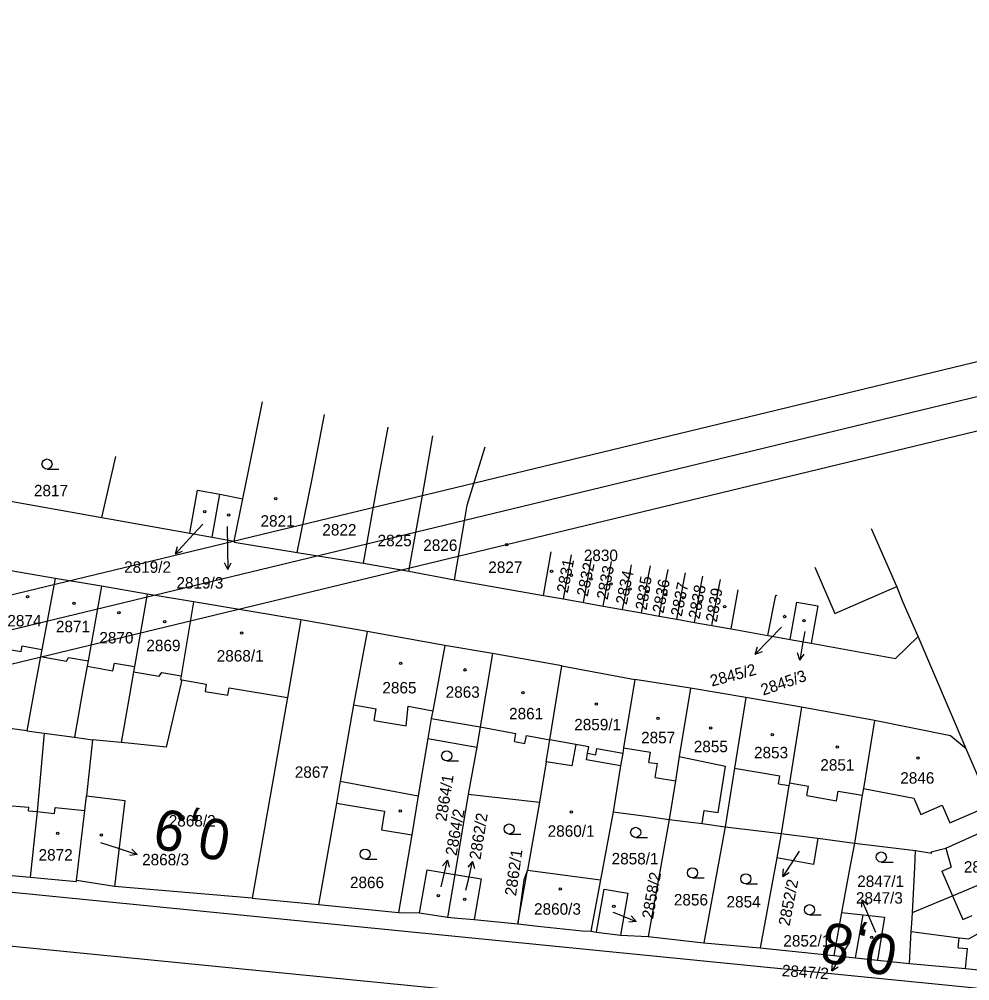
# Model space of a CAD drawing. Extents: x -738085 to -734306, y -1122197 to -1119753.
# Drawn here: x -734886.7 to -734745.8, y -1120127 to -1119984.4 of the extents above; entities that cross this region are included whole.
import ezdxf

# ---------------------------------------------------------------- set-up
doc = ezdxf.new("R2010")
doc.units = 0
for name, color, linetype in [('Hranice parcel', 7, 'Continuous'), ('Parcelní čísla', 7, 'Continuous'), ('Pop  PČ popisy', 7, 'Continuous'), ('Vnitřní kresba', 7, 'Continuous'), ('Vrstva 1', 7, 'Continuous'), ('Vrstva 7', 7, 'Continuous'), ('Značky budov', 7, 'Continuous'), ('Značky kultur', 7, 'Continuous')]:
    doc.layers.add(name, color=color, linetype=linetype)

msp = doc.modelspace()

# ---------------------------------------------------------------- linework, layer by layer
at = {"layer": 'Hranice parcel'}
for p, q in [((-734874.44, -1120058.28), (-734872.37, -1120049.21)), ((-734893, -1120054.98), (-734874.44, -1120058.28)), ((-734858.08, -1120061.19), (-734856.95, -1120054.8)), ((-734856.95, -1120054.8), (-734853.51, -1120055.5)), ((-734854.79, -1120061.77), (-734853.51, -1120055.5)), ((-734874.44, -1120058.28), (-734861.39, -1120060.6)), ((-734861.39, -1120060.6), (-734858.08, -1120061.19)), ((-734858.08, -1120061.19), (-734854.79, -1120061.77)), ((-734845.44, -1120063.49), (-734835.62, -1120065.05)), ((-734808.93, -1120069.83), (-734807.8, -1120063.35)), ((-734805.99, -1120070.36), (-734804.82, -1120063.83)), ((-734803.04, -1120070.88), (-734801.85, -1120064.32)), ((-734800.1, -1120071.41), (-734798.88, -1120064.8)), ((-734881.34, -1120067.31), (-734887.91, -1120066.19)), ((-734835.62, -1120065.05), (-734828.89, -1120066.24)), ((-734828.89, -1120066.24), (-734822.16, -1120067.53)), ((-734874.49, -1120068.47), (-734881.34, -1120067.31)), ((-734822.16, -1120067.53), (-734808.93, -1120069.83)), ((-734867.71, -1120069.63), (-734874.49, -1120068.47)), ((-734860.82, -1120070.8), (-734867.71, -1120069.63)), ((-734808.93, -1120069.83), (-734805.99, -1120070.36)), ((-734805.99, -1120070.36), (-734803.04, -1120070.88)), ((-734844.9, -1120073.45), (-734860.82, -1120070.8)), ((-734803.04, -1120070.88), (-734800.1, -1120071.41)), ((-734800.1, -1120071.41), (-734797.25, -1120071.92)), ((-734797.25, -1120071.92), (-734794.41, -1120072.43)), ((-734772.36, -1120076.38), (-734771.37, -1120070.82)), ((-734844.9, -1120073.45), (-734846.88, -1120084.98)), ((-734835.1, -1120075.16), (-734844.9, -1120073.45)), ((-734794.41, -1120072.43), (-734791.8, -1120072.9)), ((-734791.8, -1120072.9), (-734789.18, -1120073.36)), ((-734789.18, -1120073.36), (-734786.58, -1120073.83)), ((-734786.58, -1120073.83), (-734783.98, -1120074.29)), ((-734823.55, -1120077.28), (-734835.1, -1120075.16)), ((-734772.36, -1120076.38), (-734769.29, -1120076.93)), ((-734746.27, -1120092.6), (-734753.42, -1120075.94)), ((-734816.52, -1120078.43), (-734823.55, -1120077.28)), ((-734806.22, -1120080.28), (-734816.52, -1120078.43)), ((-734806.22, -1120080.28), (-734795.41, -1120082.28)), ((-734787.16, -1120083.57), (-734795.41, -1120082.28)), ((-734778.96, -1120084.96), (-734787.16, -1120083.57)), ((-734770.72, -1120086.41), (-734778.96, -1120084.96)), ((-734846.88, -1120084.98), (-734852.12, -1120114.74)), ((-734759.88, -1120088.36), (-734770.72, -1120086.41)), ((-734885.55, -1120089.9), (-734892.21, -1120088.99)), ((-734885.55, -1120089.9), (-734882.98, -1120090.25)), ((-734882.98, -1120090.25), (-734878.49, -1120090.86)), ((-734878.49, -1120090.86), (-734875.79, -1120091.23)), ((-734875.79, -1120091.23), (-734876.71, -1120099.56)), ((-734871.55, -1120091.66), (-734875.79, -1120091.23)), ((-734826.08, -1120091.05), (-734818.85, -1120092.33)), ((-734818.85, -1120092.33), (-734820.11, -1120099.3)), ((-734808.57, -1120094.5), (-734809.56, -1120100.51)), ((-734797.51, -1120095.11), (-734798.62, -1120101.92)), ((-734839.64, -1120100.63), (-734842.28, -1120115.65)), ((-734820.11, -1120099.3), (-734822.09, -1120111.23)), ((-734820.11, -1120099.3), (-734809.56, -1120100.51)), ((-734809.56, -1120100.51), (-734811.34, -1120110.59)), ((-734798.62, -1120101.92), (-734800.51, -1120112.02)), ((-734790.32, -1120103.04), (-734793.44, -1120120.43)), ((-734782.01, -1120104.13), (-734785.17, -1120121.34)), ((-734782.01, -1120104.13), (-734773.69, -1120105.13)), ((-734828.49, -1120105.32), (-734830.44, -1120116.83)), ((-734773.69, -1120105.13), (-734774.36, -1120108.76)), ((-734773.69, -1120105.13), (-734768.28, -1120105.84)), ((-734768.28, -1120105.84), (-734762.86, -1120106.55)), ((-734762.86, -1120106.55), (-734753.79, -1120107.64)), ((-734774.36, -1120108.76), (-734776.81, -1120122.08)), ((-734811.34, -1120110.59), (-734800.51, -1120112.02)), ((-734894.05, -1120110.78), (-734885.03, -1120111.61)), ((-734800.51, -1120112.02), (-734801.94, -1120119.63)), ((-734872.52, -1120112.98), (-734878.17, -1120112.12)), ((-734852.12, -1120114.74), (-734872.52, -1120112.98)), ((-734852.12, -1120114.74), (-734842.28, -1120115.65)), ((-734842.28, -1120115.65), (-734830.44, -1120116.83)), ((-734830.44, -1120116.83), (-734827.33, -1120116.92)), ((-734827.33, -1120116.92), (-734823.17, -1120117.53)), ((-734764.76, -1120116.86), (-734765.93, -1120123.22)), ((-734764.76, -1120116.86), (-734761.58, -1120117.21)), ((-734762.69, -1120123.56), (-734761.58, -1120117.21)), ((-734819.22, -1120117.87), (-734812.75, -1120118.54)), ((-734801.94, -1120119.63), (-734801.07, -1120119.77)), ((-734801.07, -1120119.77), (-734797.51, -1120120.19)), ((-734797.51, -1120120.19), (-734793.44, -1120120.43)), ((-734754.69, -1120124.4), (-734754.43, -1120119.69)), ((-734785.17, -1120121.34), (-734776.81, -1120122.08)), ((-734776.81, -1120122.08), (-734765.93, -1120123.22)), ((-734765.93, -1120123.22), (-734762.69, -1120123.56)), ((-734762.69, -1120123.56), (-734759.45, -1120123.9)), ((-734759.45, -1120123.9), (-734754.69, -1120124.4))]:
    msp.add_line(p, q, dxfattribs=at)
for points in [[(-734853.51, -1120055.5), (-734852.58, -1120050.93), (-734850.58, -1120041.13)], [(-734845.44, -1120063.49), (-734843.26, -1120052.53), (-734841.43, -1120042.99)], [(-734835.62, -1120065.05), (-734833.71, -1120054.16), (-734831.99, -1120044.9)], [(-734828.89, -1120066.24), (-734826.91, -1120055.32), (-734825.35, -1120046.18)], [(-734822.16, -1120067.53), (-734820.57, -1120058.24), (-734820.26, -1120056.46), (-734817.58, -1120047.82)], [(-734861.39, -1120060.6), (-734860.26, -1120054.21), (-734856.95, -1120054.8)], [(-734753.42, -1120075.94), (-734755.61, -1120070.88), (-734756.59, -1120068.49), (-734760.34, -1120059.94)], [(-734854.79, -1120061.77), (-734854.82, -1120061.93), (-734845.44, -1120063.49)], [(-734797.25, -1120071.92), (-734796.02, -1120065.89), (-734795.9, -1120065.28)], [(-734794.41, -1120072.43), (-734793.26, -1120066.43), (-734793.07, -1120065.46)], [(-734791.8, -1120072.9), (-734790.67, -1120066.94), (-734790.48, -1120065.97)], [(-734881.34, -1120067.31), (-734883.33, -1120077.85), (-734883.5, -1120078.88), (-734884.14, -1120082.31), (-734885.55, -1120089.9)], [(-734789.18, -1120073.36), (-734788.08, -1120067.45), (-734787.89, -1120066.48)], [(-734786.58, -1120073.83), (-734785.5, -1120067.96), (-734785.31, -1120066.99)], [(-734783.98, -1120074.29), (-734782.92, -1120068.47), (-734782.73, -1120067.49)], [(-734874.49, -1120068.47), (-734876.47, -1120079.55), (-734876.61, -1120080.32), (-734877.23, -1120083.78), (-734878.49, -1120090.86)], [(-734867.71, -1120069.63), (-734869.58, -1120080.38), (-734869.72, -1120081.15), (-734870.32, -1120084.61), (-734871.55, -1120091.66)], [(-734775.69, -1120075.78), (-734774.51, -1120069.82), (-734774.35, -1120069.85)], [(-734860.82, -1120070.8), (-734862.64, -1120081.76), (-734862.74, -1120082.33), (-734862.58, -1120082.36)], [(-734771.37, -1120070.82), (-734768.3, -1120071.37), (-734769.29, -1120076.93)], [(-734783.98, -1120074.29), (-734781.14, -1120074.8), (-734775.69, -1120075.78)], [(-734835.1, -1120075.16), (-734837.09, -1120086.08), (-734839.07, -1120097.38), (-734839.64, -1120100.63)], [(-734775.69, -1120075.78), (-734775.36, -1120075.84), (-734772.36, -1120076.38)], [(-734769.29, -1120076.93), (-734756.74, -1120079.17), (-734753.42, -1120075.94)], [(-734823.55, -1120077.28), (-734825.37, -1120086.94), (-734825.58, -1120088.08), (-734826.08, -1120091.05)], [(-734816.52, -1120078.43), (-734818.33, -1120089.33), (-734818.85, -1120092.33)], [(-734808.57, -1120094.5), (-734808.03, -1120091.23), (-734806.22, -1120080.28)], [(-734862.58, -1120082.36), (-734864.87, -1120092.33), (-734870.01, -1120091.81), (-734871.55, -1120091.66)], [(-734862.58, -1120082.36), (-734858.94, -1120082.97), (-734859.12, -1120084.06), (-734855.72, -1120084.64), (-734855.53, -1120083.53), (-734846.88, -1120084.98)], [(-734795.41, -1120082.28), (-734797.07, -1120092.45), (-734797.2, -1120093.23), (-734797.51, -1120095.11)], [(-734787.16, -1120083.57), (-734788.81, -1120093.71), (-734789.39, -1120097.33), (-734790.32, -1120103.04)], [(-734778.96, -1120084.96), (-734780.63, -1120095.44), (-734782.01, -1120104.13)], [(-734770.72, -1120086.41), (-734772.5, -1120097.61), (-734772.56, -1120098.03), (-734773.69, -1120105.13)], [(-734759.88, -1120088.36), (-734761.53, -1120098.46), (-734761.7, -1120099.46), (-734762.86, -1120106.55)], [(-734746.27, -1120092.6), (-734748.62, -1120090.64), (-734759.88, -1120088.36)], [(-734882.98, -1120090.25), (-734884.03, -1120101.9), (-734885.03, -1120111.61)], [(-734826.08, -1120091.05), (-734827.52, -1120099.56), (-734828.49, -1120105.32)], [(-734797.51, -1120095.11), (-734802.57, -1120094.22), (-734802.4, -1120093.24), (-734802.22, -1120092.3), (-734804.16, -1120091.94), (-734804.75, -1120095.12), (-734808.57, -1120094.5)], [(-734741.41, -1120103.73), (-734742.65, -1120100.94), (-734743.81, -1120098.34), (-734746.27, -1120092.6)], [(-734878.17, -1120112.12), (-734876.95, -1120101.73), (-734876.71, -1120099.56)], [(-734876.71, -1120099.56), (-734871.01, -1120100.25), (-734872.52, -1120112.98)], [(-734839.64, -1120100.63), (-734832.51, -1120101.83), (-734832.97, -1120104.57), (-734828.49, -1120105.32)], [(-734798.62, -1120101.92), (-734793.71, -1120102.56), (-734790.32, -1120103.04)], [(-734732.31, -1120124.29), (-734735.07, -1120127.22), (-734738.9, -1120128.4), (-734741.96, -1120128.37), (-734978.31, -1120104.89), (-734995.05, -1120103.5), (-735001.08, -1120103.64), (-735005.96, -1120104.65), (-735026.65, -1120111.99), (-735048.37, -1120119.26), (-735164.14, -1120157.32), (-735176.88, -1120160.91), (-735184.81, -1120162.43), (-735185.96, -1120162.53), (-735190.85, -1120162.98), (-735196.87, -1120162.75), (-735201.79, -1120161.48), (-735203.71, -1120160.98), (-735206.41, -1120159.5), (-735208.64, -1120157.56), (-735225.14, -1120141.26)], [(-734790.32, -1120103.04), (-734785.41, -1120103.64), (-734782.01, -1120104.13)], [(-734753.79, -1120107.64), (-734751.4, -1120108.03), (-734751.46, -1120107.88), (-734749.29, -1120107.32), (-734741.41, -1120103.73)], [(-734768.28, -1120105.84), (-734768.92, -1120109.73), (-734774.36, -1120108.76)], [(-734762.86, -1120106.55), (-734763.62, -1120110.68), (-734764.76, -1120116.86)], [(-734754.25, -1120116.86), (-734754.12, -1120114.04), (-734753.92, -1120110.19), (-734753.79, -1120107.64)], [(-734827.33, -1120116.92), (-734827.28, -1120116.65), (-734826.18, -1120110.52), (-734822.09, -1120111.23)], [(-734811.34, -1120110.59), (-734811.85, -1120111.99), (-734812.75, -1120118.54)], [(-734754.25, -1120116.86), (-734748.32, -1120114.37), (-734738.55, -1120110.28)], [(-735187.2, -1120177.07), (-735186.92, -1120175.94), (-735186.47, -1120174.12), (-735185.21, -1120172.48), (-735182.42, -1120171.13), (-735165.98, -1120166.38), (-735013.95, -1120116.34), (-735003.48, -1120113.01), (-735000.64, -1120112.19), (-735000, -1120112.13), (-734996.62, -1120111.83), (-734988.63, -1120112.11), (-734951.68, -1120115.51), (-734795.1, -1120131), (-734756.12, -1120134.99), (-734754.2, -1120137.32), (-734753.31, -1120137.78), (-734734.93, -1120139.52), (-734728.17, -1120141.08), (-734724.68, -1120142.84), (-734723.73, -1120143.69)], [(-734885.03, -1120111.61), (-734878.18, -1120112.24), (-734878.17, -1120112.12)], [(-734822.09, -1120111.23), (-734823.15, -1120117.32), (-734823.17, -1120117.53)], [(-734822.09, -1120111.23), (-734818.2, -1120111.85), (-734819.22, -1120117.87)], [(-734801.07, -1120119.77), (-734799.95, -1120113.38), (-734796.45, -1120113.97), (-734797.51, -1120120.19)], [(-734823.17, -1120117.53), (-734821.66, -1120117.71), (-734819.22, -1120117.87)], [(-734761.58, -1120117.21), (-734758.4, -1120117.56), (-734759.45, -1120123.9)], [(-734754.43, -1120119.69), (-734747.32, -1120120.59), (-734745.89, -1120120.77), (-734744.27, -1120119.8), (-734735.7, -1120116.71)], [(-734754.43, -1120119.69), (-734754.35, -1120118.5), (-734754.25, -1120116.86)], [(-734812.75, -1120118.54), (-734809.77, -1120118.87), (-734803.22, -1120119.55), (-734801.94, -1120119.63)], [(-734793.44, -1120120.43), (-734791.72, -1120120.63), (-734785.17, -1120121.34)], [(-734754.69, -1120124.4), (-734746.39, -1120125.14), (-734738.56, -1120125.97), (-734734.16, -1120120.2)]]:
    msp.add_lwpolyline(points, dxfattribs=at)
at = {"layer": 'Pop  PČ popisy'}
for p, q in [((-734859.47, -1120059.28), (-734861.47, -1120061.45)), ((-734855.83, -1120059.6), (-734855.79, -1120062.99)), ((-734861.47, -1120061.45), (-734863.52, -1120063.65)), ((-734863.52, -1120063.65), (-734863.2, -1120062.57)), ((-734863.52, -1120063.65), (-734862.47, -1120063.25)), ((-734855.79, -1120062.99), (-734855.74, -1120065.99)), ((-734855.74, -1120065.99), (-734856.26, -1120065)), ((-734855.74, -1120065.99), (-734855.25, -1120064.98)), ((-734773.66, -1120074.55), (-734775.46, -1120076.38)), ((-734775.46, -1120076.38), (-734777.55, -1120078.54)), ((-734770.21, -1120075.2), (-734770.45, -1120076.48)), ((-734777.55, -1120078.54), (-734777.21, -1120077.47)), ((-734770.45, -1120076.48), (-734770.97, -1120079.44)), ((-734777.55, -1120078.54), (-734776.49, -1120078.17)), ((-734770.97, -1120079.44), (-734771.29, -1120078.36)), ((-734770.97, -1120079.44), (-734770.3, -1120078.54)), ((-734874.64, -1120106.48), (-734872.02, -1120107.31)), ((-734872.02, -1120107.31), (-734869.17, -1120108.24)), ((-734869.17, -1120108.24), (-734869.96, -1120107.45)), ((-734771.06, -1120107.75), (-734771.86, -1120108.99)), ((-734869.17, -1120108.24), (-734870.27, -1120108.4)), ((-734823.19, -1120109.07), (-734823.9, -1120109.93)), ((-734823.86, -1120111.99), (-734823.19, -1120109.07)), ((-734823.19, -1120109.07), (-734822.92, -1120110.15)), ((-734771.86, -1120108.99), (-734773.49, -1120111.51)), ((-734819.45, -1120109.27), (-734820.17, -1120110.13)), ((-734820.13, -1120112.19), (-734819.45, -1120109.27)), ((-734819.45, -1120109.27), (-734819.19, -1120110.35)), ((-734773.49, -1120111.51), (-734773.37, -1120110.39)), ((-734824.1, -1120113.03), (-734823.86, -1120111.99)), ((-734773.49, -1120111.51), (-734772.53, -1120110.94)), ((-734820.45, -1120113.54), (-734820.13, -1120112.19)), ((-734761.74, -1120114.97), (-734761.81, -1120116.08)), ((-734760.57, -1120117.73), (-734761.74, -1120114.97)), ((-734761.74, -1120114.97), (-734760.89, -1120115.69)), ((-734798.65, -1120116.78), (-734797.97, -1120117.06)), ((-734797.97, -1120117.06), (-734795.19, -1120118.18)), ((-734795.19, -1120118.18), (-734795.93, -1120117.34)), ((-734759.69, -1120119.84), (-734760.57, -1120117.73)), ((-734795.19, -1120118.18), (-734796.3, -1120118.27)), ((-734763.55, -1120121.15), (-734764.64, -1120122.94)), ((-734764.64, -1120122.94), (-734766.19, -1120125.51)), ((-734766.19, -1120125.51), (-734766.1, -1120124.4)), ((-734766.19, -1120125.51), (-734765.24, -1120124.91))]:
    msp.add_line(p, q, dxfattribs=at)
at = {"layer": 'Vnitřní kresba'}
for p, q in [((-734768.73, -1120065.66), (-734765.76, -1120072.52)), ((-734781.14, -1120074.8), (-734780.1, -1120069.02)), ((-734765.76, -1120072.52), (-734756.59, -1120068.49)), ((-734890.23, -1120077.53), (-734886.38, -1120078.15)), ((-734886.38, -1120078.15), (-734886.22, -1120077.31)), ((-734886.22, -1120077.31), (-734883.33, -1120077.85)), ((-734883.5, -1120078.88), (-734879.66, -1120079.59)), ((-734879.66, -1120079.59), (-734879.37, -1120079.03)), ((-734879.37, -1120079.03), (-734876.47, -1120079.55)), ((-734876.61, -1120080.32), (-734872.77, -1120081.01)), ((-734872.77, -1120081.01), (-734872.54, -1120079.86)), ((-734872.54, -1120079.86), (-734869.58, -1120080.38)), ((-734869.72, -1120081.15), (-734865.92, -1120081.81)), ((-734865.92, -1120081.81), (-734865.53, -1120081.28)), ((-734865.53, -1120081.28), (-734862.64, -1120081.76)), ((-734837.09, -1120086.08), (-734833.74, -1120086.67)), ((-734829.29, -1120089.18), (-734829.01, -1120086.25)), ((-734829.01, -1120086.25), (-734825.37, -1120086.94)), ((-734834.04, -1120088.37), (-734833.74, -1120086.67)), ((-734834.04, -1120088.37), (-734829.29, -1120089.18)), ((-734825.58, -1120088.08), (-734818.33, -1120089.33)), ((-734818.33, -1120089.33), (-734813.05, -1120090.3)), ((-734813.27, -1120091.5), (-734813.05, -1120090.3)), ((-734811.69, -1120091.8), (-734811.47, -1120090.59)), ((-734811.47, -1120090.59), (-734808.03, -1120091.23)), ((-734813.27, -1120091.5), (-734811.69, -1120091.8)), ((-734804.16, -1120091.94), (-734808.03, -1120091.23)), ((-734802.4, -1120093.24), (-734801.19, -1120093.46)), ((-734801.19, -1120093.46), (-734801.02, -1120092.52)), ((-734801.02, -1120092.52), (-734797.2, -1120093.23)), ((-734797.07, -1120092.45), (-734793.1, -1120093.06)), ((-734793.34, -1120094.6), (-734793.1, -1120093.06)), ((-734793.34, -1120094.6), (-734792.05, -1120094.77)), ((-734792.39, -1120096.85), (-734792.05, -1120094.77)), ((-734788.81, -1120093.71), (-734781.97, -1120095.16)), ((-734783.04, -1120102.01), (-734781.97, -1120095.16)), ((-734780.63, -1120095.44), (-734773.92, -1120096.61)), ((-734839.07, -1120097.38), (-734827.52, -1120099.56)), ((-734792.39, -1120096.85), (-734789.39, -1120097.33)), ((-734774.12, -1120097.76), (-734773.92, -1120096.61)), ((-734774.12, -1120097.76), (-734772.56, -1120098.03)), ((-734772.5, -1120097.61), (-734769.66, -1120098.1)), ((-734769.9, -1120099.5), (-734769.66, -1120098.1)), ((-734765.5, -1120100.27), (-734765.26, -1120098.85)), ((-734765.26, -1120098.85), (-734761.7, -1120099.46)), ((-734761.53, -1120098.46), (-734754.05, -1120099.92)), ((-734769.9, -1120099.5), (-734765.5, -1120100.27)), ((-734754.05, -1120099.92), (-734753.01, -1120102.32)), ((-734889.05, -1120100.92), (-734885.26, -1120101.22)), ((-734885.3, -1120101.77), (-734885.26, -1120101.22)), ((-734885.3, -1120101.77), (-734884.03, -1120101.9)), ((-734884.03, -1120101.9), (-734881.44, -1120102.15)), ((-734881.44, -1120102.15), (-734881.34, -1120101.26)), ((-734881.34, -1120101.26), (-734876.95, -1120101.73)), ((-734785.41, -1120103.64), (-734785.13, -1120101.71)), ((-734785.13, -1120101.71), (-734783.04, -1120102.01)), ((-734753.01, -1120102.32), (-734749.84, -1120100.95)), ((-734749.84, -1120100.95), (-734748.71, -1120103.56)), ((-734748.71, -1120103.56), (-734742.65, -1120100.94)), ((-734749.29, -1120107.32), (-734748.53, -1120110.13)), ((-734812.75, -1120118.54), (-734811.34, -1120110.59)), ((-734749.9, -1120110.72), (-734748.53, -1120110.13)), ((-734749.9, -1120110.72), (-734748.32, -1120114.37)), ((-734748.32, -1120114.37), (-734746.8, -1120117.88)), ((-734746.8, -1120117.88), (-734745.41, -1120117.28)), ((-734747.48, -1120122.09), (-734747.32, -1120120.59)), ((-734747.48, -1120122.09), (-734746.1, -1120122.21)), ((-734746.39, -1120125.14), (-734746.1, -1120122.21))]:
    msp.add_line(p, q, dxfattribs=at)
at = {"layer": 'Vrstva 1'}
for points in [[(-734534.27, -1119984.39), (-735554.91, -1120230.88), (-735485.2, -1120519.57), (-734464.55, -1120273.08)], [(-734470.58, -1120269.4), (-735481.51, -1120513.53), (-735548.88, -1120234.56), (-734537.95, -1119990.43)], [(-734541.63, -1119996.45), (-735348.44, -1120191.3), (-735283.42, -1120460.56), (-734476.61, -1120265.71)]]:
    msp.add_lwpolyline(points, close=True, dxfattribs=at)
at = {"layer": 'Značky budov'}
for centre in [(-734848.65, -1120055.47), (-734859.16, -1120057.42), (-734855.6, -1120057.9), (-734814.39, -1120062.33), (-734807.76, -1120066.24), (-734804.8, -1120066.84), (-734801.91, -1120067.4), (-734798.96, -1120068.16), (-734796.12, -1120068.87), (-734793.53, -1120069.27), (-734885.44, -1120070), (-734790.83, -1120069.7), (-734788.23, -1120070.18), (-734785.72, -1120070.82), (-734878.55, -1120071), (-734782.09, -1120071.5), (-734871.9, -1120072.39), (-734865.1, -1120073.73), (-734773.2, -1120072.96), (-734770.33, -1120073.6), (-734853.71, -1120075.42), (-734830.11, -1120079.91), (-734820.57, -1120080.87), (-734812, -1120084.26), (-734801.1, -1120085.94), (-734791.98, -1120088.07), (-734784.17, -1120089.49), (-734775.04, -1120090.5), (-734765.4, -1120092.33), (-734753.43, -1120093.95), (-734830.19, -1120101.81), (-734804.84, -1120101.94), (-734880.95, -1120105.11), (-734874.49, -1120105.35), (-734806.47, -1120113.35), (-734824.54, -1120114.34), (-734820.63, -1120114.88), (-734798.52, -1120115.96), (-734763.56, -1120120), (-734760.29, -1120120.54)]:
    msp.add_circle(centre, 0.175, dxfattribs=at)
at = {"layer": 'Značky kultur'}
for p, q in [((-734882.55, -1120051.1), (-734880.8, -1120051.1)), ((-734823.3, -1120094.38), (-734821.55, -1120094.38)), ((-734814.04, -1120105.22), (-734812.29, -1120105.22)), ((-734795.28, -1120105.72), (-734793.53, -1120105.72)), ((-734835.38, -1120108.94), (-734833.63, -1120108.94)), ((-734758.87, -1120109.38), (-734757.12, -1120109.38)), ((-734786.86, -1120111.71), (-734785.11, -1120111.71)), ((-734778.95, -1120112.62), (-734777.2, -1120112.62)), ((-734769.52, -1120117.19), (-734767.77, -1120117.19))]:
    msp.add_line(p, q, dxfattribs=at)
for centre in [(-734882.55, -1120050.35), (-734823.3, -1120093.63), (-734814.04, -1120104.47), (-734795.28, -1120104.97), (-734835.38, -1120108.19), (-734758.87, -1120108.63), (-734786.86, -1120110.96), (-734778.95, -1120111.87), (-734769.52, -1120116.44)]:
    msp.add_circle(centre, 0.75, dxfattribs=at)

# ---------------------------------------------------------------- texts
at = {"layer": 'Parcelní čísla'}
for s, p in [('2817', (-734884.49, -1120055.14)), ('2821', (-734850.9, -1120059.64)), ('2822', (-734841.73, -1120060.95)), ('2825', (-734833.54, -1120062.54)), ('2826', (-734826.77, -1120063.24)), ('2830', (-734802.97, -1120064.74)), ('2819/2', (-734871.12, -1120066.48)), ('2827', (-734817.13, -1120066.5)), ('2819/3', (-734863.36, -1120068.82)), ('2874', (-734888.43, -1120074.43)), ('2871', (-734881.23, -1120075.29)), ('2870', (-734874.79, -1120076.96)), ('2869', (-734867.82, -1120078.11)), ('2868/1', (-734857.39, -1120079.64)), ('2865', (-734832.83, -1120084.37)), ('2863', (-734823.45, -1120085.01)), ('2861', (-734814.05, -1120088.21)), ('2859/1', (-734804.39, -1120089.84)), ('2857', (-734794.48, -1120091.76)), ('2855', (-734786.67, -1120093.08)), ('2853', (-734777.74, -1120093.99)), ('2851', (-734767.91, -1120095.82)), ('2867', (-734845.82, -1120096.88)), ('2846', (-734756.06, -1120097.75)), ('2868/2', (-734864.5, -1120104.1)), ('2860/1', (-734808.33, -1120105.62)), ('2872', (-734883.8, -1120109.15)), ('2868/3', (-734868.45, -1120109.86)), ('2858/1', (-734798.85, -1120109.72)), ('2848', (-734746.63, -1120110.94)), ('2866', (-734837.64, -1120113.24)), ('2847/1', (-734762.44, -1120113.07)), ('2856', (-734789.62, -1120115.81)), ('2854', (-734781.81, -1120116.11)), ('2847/3', (-734762.63, -1120115.54)), ('2860/3', (-734810.35, -1120117.18)), ('2852/1', (-734773.39, -1120121.9))]:
    msp.add_text(s, height=1.7, dxfattribs=at).set_placement(p)
for s, rotation, p in [('2831', 79, (-734805.35, -1120069.56)), ('2832', 78, (-734802.4, -1120070.1)), ('2833', 79, (-734799.44, -1120070.55)), ('2834', 78, (-734796.62, -1120071.29)), ('2835', 81, (-734793.67, -1120072.1)), ('2836', 79, (-734791.17, -1120072.57)), ('2837', 78, (-734788.47, -1120073.05)), ('2838', 79, (-734785.83, -1120073.42)), ('2839', 80, (-734783.26, -1120073.87)), ('2845/2', 15, (-734783.99, -1120083.36)), ('2845/3', 19, (-734776.39, -1120084.71)), ('2864/1', 81, (-734823.34, -1120103.41)), ('2864/2', 80, (-734821.84, -1120108.51)), ('2862/2', 81, (-734818.29, -1120109.1)), ('2862/1', 82, (-734813.02, -1120114.47)), ('2858/2', 80, (-734792.71, -1120117.88)), ('2852/2', 79, (-734772.48, -1120118.94)), ('2847/2', 356, (-734773.66, -1120126.28))]:
    msp.add_text(s, height=1.7, rotation=rotation, dxfattribs=at).set_placement(p)
at = {"layer": 'Vrstva 7'}
for s, rotation, p in [('0,9', 169.221, (-734854.99, -1120103.43)), ('0,8', 167.2679, (-734756.09, -1120120.57))]:
    msp.add_text(s, height=6, rotation=rotation, dxfattribs=at).set_placement(p)

doc.saveas('drawing.dxf')
